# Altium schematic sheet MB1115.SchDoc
size A4; DocumentNumber: 1; Revision: B.2(PCB.SCH); SheetNumber: 1; SheetTotal: 6; PageSetup: Record=PageOptions|CenterHorizontal=True|CenterVertical=True|PrintScale=1.00|XCorrection=1.00|YCorrection=1.00|PrintKind=1|BorderSize=5000000|LeftOffset=0|BottomOffset=0|Orientation=2|PaperLength=1000|PaperWidth=1000|Scale=100|PaperSource=15|PrintQuality=1200|MediaType=1|DitherType=10|PaperKind=A4|PrintScaleMode=1
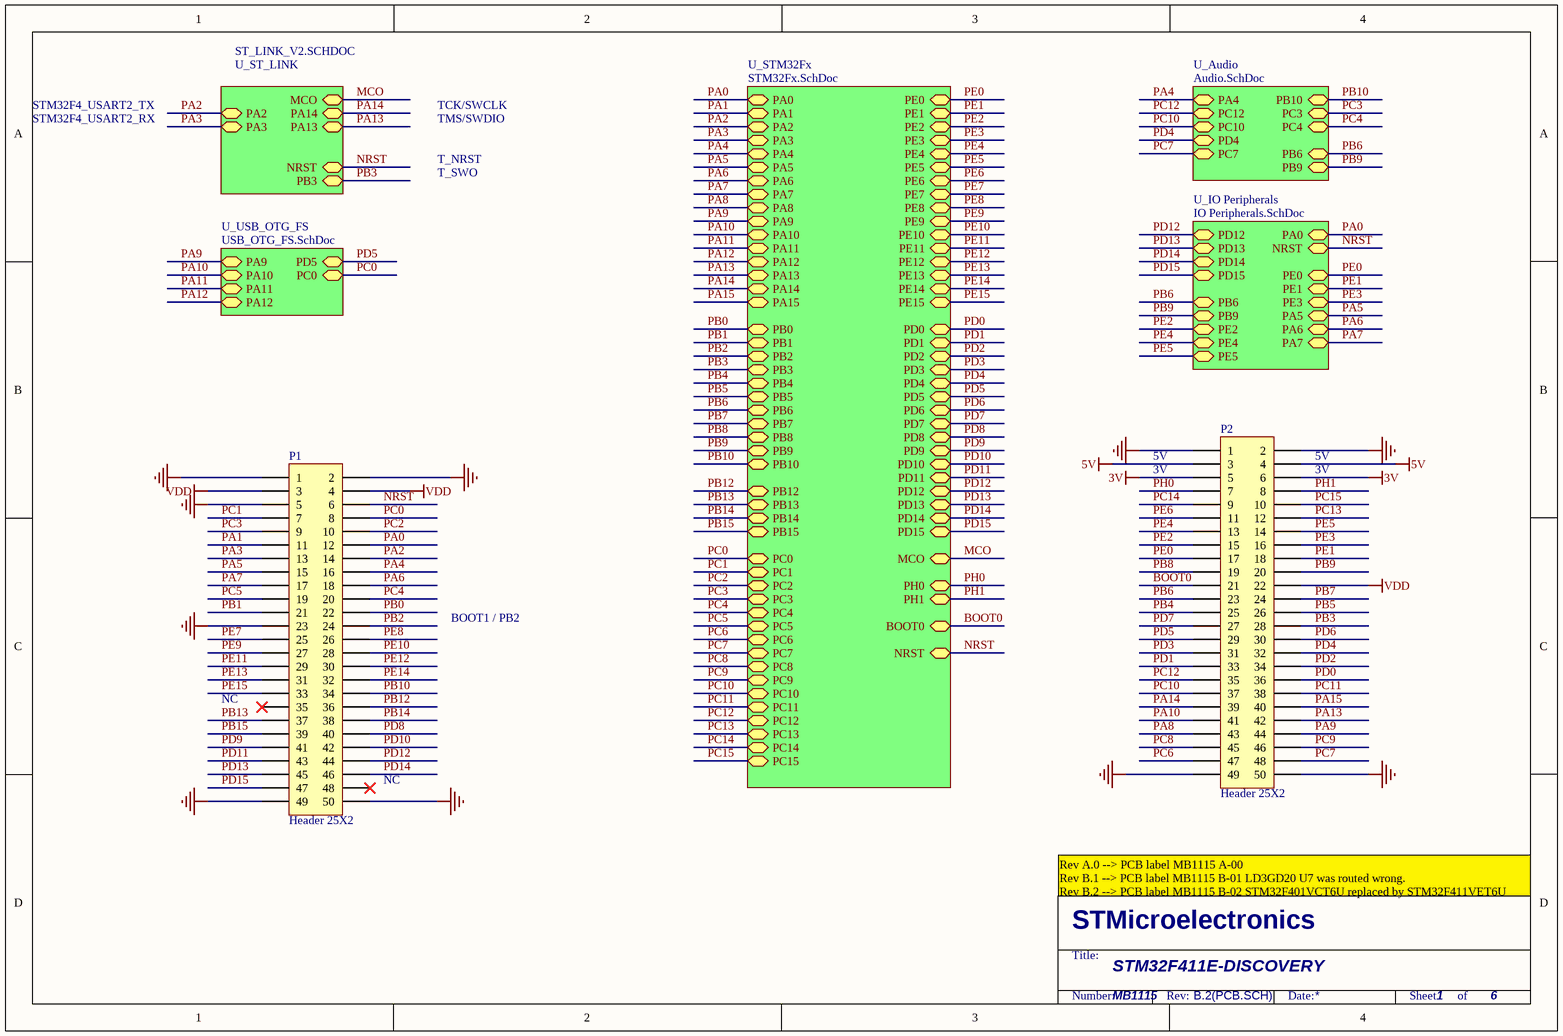
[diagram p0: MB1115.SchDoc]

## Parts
P1  Header 25X2  [HDR2X25]
P2  Header 25X2  [HDR2X25]

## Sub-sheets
U_Audio = Audio.SchDoc: PA4, PC12, PC10, PD4, PC7, PC3, PB10, PC4, PB6, PB9
U_IO Peripherals = IO Peripherals.SchDoc: PA0, NRST, PE0, PE1, PE3, PA5, PA7, PA6, PE4, PE5, PE2, PB6, PB9, PD12, PD13, PD14, PD15
U_ST_LINK = ST_LINK_V2.SCHDOC: PA13, PA14, NRST, PB3, MCO, PA3, PA2
U_STM32Fx = STM32Fx.SchDoc: PD2, BOOT0, PH1, PH0, NRST, PE0, PE1, PE2, PE3, PE4, PE5, PE6, PE7, PE8, PE9, PE10, PE11, PE12, PE13, PE14, PE15, PD0, PD1, PD3, PD4, PD5, PD6, PD7, PD8, PD9, PD10, PD11, PD12, PD13, PD14, PD15, MCO, PA1, PA2, PA3, PA4, PA5, PA6, PA7, PA8, PA9, PA10, PA11, PA12, PA13, PA14, PA15, PB1, PB2, PB3, PB4, PB5, PB6, PB7, PB8, PB9, PB10, PB12, PB13, PB14, PB15, PC1, PC2, PC3, PC4, PC5, PC6, PC7, PC8, PC9, PC10, PC11, PC12, PC13, PA0, PB0, PC0, PC14, PC15
U_USB_OTG_FS = USB_OTG_FS.SchDoc: PC0, PD5, PA9, PA10, PA11, PA12

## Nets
3V: P2.5 P2.6
5V: P2.3 P2.4
GND: P1.1 P1.2 P1.5 P1.23 P1.49 P1.50 P2.1 P2.2 P2.49 P2.50
VDD: P1.3 P1.4 P2.22
BOOT0: P2.21 ; sheet U_STM32Fx/BOOT0
MCO: sheet U_ST_LINK/MCO, sheet U_STM32Fx/MCO
NRST: P1.6 ; sheet U_ST_LINK/NRST, sheet U_IO Peripherals/NRST, sheet U_STM32Fx/NRST
PA0: P1.12 ; sheet U_IO Peripherals/PA0, sheet U_STM32Fx/PA0
PA1: P1.11 ; sheet U_STM32Fx/PA1
PA2: P1.14 ; sheet U_ST_LINK/PA2, sheet U_STM32Fx/PA2
PA3: P1.13 ; sheet U_ST_LINK/PA3, sheet U_STM32Fx/PA3
PA4: P1.16 ; sheet U_Audio/PA4, sheet U_STM32Fx/PA4
PA5: P1.15 ; sheet U_IO Peripherals/PA5, sheet U_STM32Fx/PA5
PA6: P1.18 ; sheet U_IO Peripherals/PA6, sheet U_STM32Fx/PA6
PA7: P1.17 ; sheet U_IO Peripherals/PA7, sheet U_STM32Fx/PA7
PA8: P2.43 ; sheet U_STM32Fx/PA8
PA9: P2.44 ; sheet U_STM32Fx/PA9, sheet U_USB_OTG_FS/PA9
PA10: P2.41 ; sheet U_STM32Fx/PA10, sheet U_USB_OTG_FS/PA10
PA11: sheet U_STM32Fx/PA11, sheet U_USB_OTG_FS/PA11
PA12: sheet U_STM32Fx/PA12, sheet U_USB_OTG_FS/PA12
PA13: P2.42 ; sheet U_ST_LINK/PA13, sheet U_STM32Fx/PA13
PA14: P2.39 ; sheet U_ST_LINK/PA14, sheet U_STM32Fx/PA14
PA15: P2.40 ; sheet U_STM32Fx/PA15
PB0: P1.22 ; sheet U_STM32Fx/PB0
PB1: P1.21 ; sheet U_STM32Fx/PB1
PB2: P1.24 ; sheet U_STM32Fx/PB2
PB3: P2.28 ; sheet U_ST_LINK/PB3, sheet U_STM32Fx/PB3
PB4: P2.25 ; sheet U_STM32Fx/PB4
PB5: P2.26 ; sheet U_STM32Fx/PB5
PB6: P2.23 ; sheet U_Audio/PB6, sheet U_IO Peripherals/PB6, sheet U_STM32Fx/PB6
PB7: P2.24 ; sheet U_STM32Fx/PB7
PB8: P2.19 ; sheet U_STM32Fx/PB8
PB9: P2.20 ; sheet U_Audio/PB9, sheet U_IO Peripherals/PB9, sheet U_STM32Fx/PB9
PB10: P1.34 ; sheet U_Audio/PB10, sheet U_STM32Fx/PB10
PB12: P1.36 ; sheet U_STM32Fx/PB12
PB13: P1.37 ; sheet U_STM32Fx/PB13
PB14: P1.38 ; sheet U_STM32Fx/PB14
PB15: P1.39 ; sheet U_STM32Fx/PB15
PC0: P1.8 ; sheet U_STM32Fx/PC0, sheet U_USB_OTG_FS/PC0
PC1: P1.7 ; sheet U_STM32Fx/PC1
PC2: P1.10 ; sheet U_STM32Fx/PC2
PC3: P1.9 ; sheet U_Audio/PC3, sheet U_STM32Fx/PC3
PC4: P1.20 ; sheet U_Audio/PC4, sheet U_STM32Fx/PC4
PC5: P1.19 ; sheet U_STM32Fx/PC5
PC6: P2.47 ; sheet U_STM32Fx/PC6
PC7: P2.48 ; sheet U_Audio/PC7, sheet U_STM32Fx/PC7
PC8: P2.45 ; sheet U_STM32Fx/PC8
PC9: P2.46 ; sheet U_STM32Fx/PC9
PC10: P2.37 ; sheet U_Audio/PC10, sheet U_STM32Fx/PC10
PC11: P2.38 ; sheet U_STM32Fx/PC11
PC12: P2.35 ; sheet U_Audio/PC12, sheet U_STM32Fx/PC12
PC13: P2.12 ; sheet U_STM32Fx/PC13
PC14: P2.9 ; sheet U_STM32Fx/PC14
PC15: P2.10 ; sheet U_STM32Fx/PC15
PD0: P2.36 ; sheet U_STM32Fx/PD0
PD1: P2.33 ; sheet U_STM32Fx/PD1
PD2: P2.34 ; sheet U_STM32Fx/PD2
PD3: P2.31 ; sheet U_STM32Fx/PD3
PD4: P2.32 ; sheet U_Audio/PD4, sheet U_STM32Fx/PD4
PD5: P2.29 ; sheet U_STM32Fx/PD5, sheet U_USB_OTG_FS/PD5
PD6: P2.30 ; sheet U_STM32Fx/PD6
PD7: P2.27 ; sheet U_STM32Fx/PD7
PD8: P1.40 ; sheet U_STM32Fx/PD8
PD9: P1.41 ; sheet U_STM32Fx/PD9
PD10: P1.42 ; sheet U_STM32Fx/PD10
PD11: P1.43 ; sheet U_STM32Fx/PD11
PD12: P1.44 ; sheet U_IO Peripherals/PD12, sheet U_STM32Fx/PD12
PD13: P1.45 ; sheet U_IO Peripherals/PD13, sheet U_STM32Fx/PD13
PD14: P1.46 ; sheet U_IO Peripherals/PD14, sheet U_STM32Fx/PD14
PD15: P1.47 ; sheet U_IO Peripherals/PD15, sheet U_STM32Fx/PD15
PE0: P2.17 ; sheet U_IO Peripherals/PE0, sheet U_STM32Fx/PE0
PE1: P2.18 ; sheet U_IO Peripherals/PE1, sheet U_STM32Fx/PE1
PE2: P2.15 ; sheet U_IO Peripherals/PE2, sheet U_STM32Fx/PE2
PE3: P2.16 ; sheet U_IO Peripherals/PE3, sheet U_STM32Fx/PE3
PE4: P2.13 ; sheet U_IO Peripherals/PE4, sheet U_STM32Fx/PE4
PE5: P2.14 ; sheet U_IO Peripherals/PE5, sheet U_STM32Fx/PE5
PE6: P2.11 ; sheet U_STM32Fx/PE6
PE7: P1.25 ; sheet U_STM32Fx/PE7
PE8: P1.26 ; sheet U_STM32Fx/PE8
PE9: P1.27 ; sheet U_STM32Fx/PE9
PE10: P1.28 ; sheet U_STM32Fx/PE10
PE11: P1.29 ; sheet U_STM32Fx/PE11
PE12: P1.30 ; sheet U_STM32Fx/PE12
PE13: P1.31 ; sheet U_STM32Fx/PE13
PE14: P1.32 ; sheet U_STM32Fx/PE14
PE15: P1.33 ; sheet U_STM32Fx/PE15
PH0: P2.7 ; sheet U_STM32Fx/PH0
PH1: P2.8 ; sheet U_STM32Fx/PH1

Not connected (* = marked no-connect by the designer): P1 35* 48*

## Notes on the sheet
- STM32F4_USART2_TX
- TCK/SWCLK
- STM32F4_USART2_RX
- TMS/SWDIO
- T_SWO
- T_NRST
- 5V
- 3V
- (near P2) 5V
- (near P2) 3V
- BOOT1 / PB2
- NC
- (near P1) NC
- Rev A.0 --> PCB label MB1115 A-00
  Rev B.1 --> PCB label MB1115 B-01 LD3GD20 U7 was routed wrong.
  Rev B.2 --> PCB label MB1115 B-02 STM32F401VCT6U replaced by STM32F411VET6U
- STM32F411E-DISCOVERY
- MB1115
- 1

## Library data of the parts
P1 P2 = Header 25X2: Header, 25-Pin, Dual row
